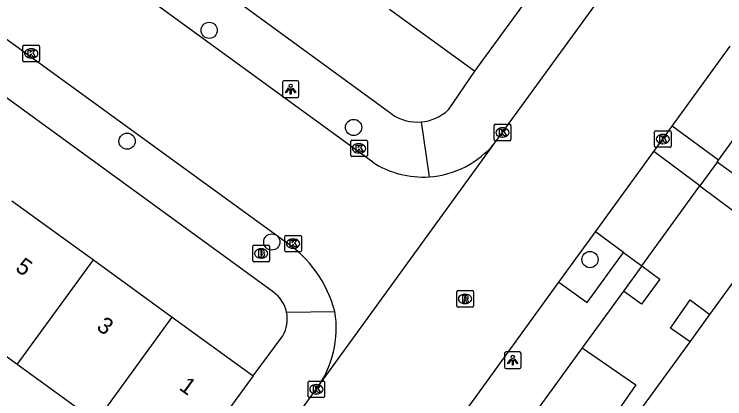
# Model space of a CAD drawing. Extents: x 159675 to 160530, y 382179 to 382901.
# Drawn here: x 160224.11 to 160266.94, y 382538.52 to 382561.72 of the extents above; entities that cross this region are included whole.
import ezdxf

# ---------------------------------------------------------------- set-up
doc = ezdxf.new("R2010")
doc.units = 0
for name, color, linetype in [('IMGEO_Boom', 7, 'Continuous'), ('IMGEO_Brandkraan', 7, 'Continuous'), ('IMGEO_Kolk', 7, 'Continuous'), ('IMGEO_Lichtpunt', 7, 'Continuous'), ('IMGEO_Pand', 7, 'Continuous'), ('IMGEO_Pand_nummerreeks', 7, 'Continuous'), ('IMGEO_Rijbaan_lokaal_gesloten', 7, 'Continuous'), ('IMGEO_Rijbaan_lokaal_open', 7, 'Continuous'), ('IMGEO_Rioolput', 7, 'Continuous'), ('IMGEO_Voetpad_open', 7, 'Continuous')]:
    doc.layers.add(name, color=color, linetype=linetype)

msp = doc.modelspace()

# ---------------------------------------------------------------- linework, layer by layer
at = {"layer": 'IMGEO_Boom'}
for centre in [(160235.859, 382560.746), (160244.564, 382554.886), (160230.912, 382554.058), (160239.635, 382547.977), (160258.813, 382546.917)]:
    msp.add_circle(centre, 0.489, dxfattribs=at)
at = {"layer": 'IMGEO_Brandkraan'}
for p, q in [((160238.567, 382547.789), (160239.419, 382547.789)), ((160238.492, 382546.863), (160238.492, 382547.715)), ((160238.98, 382547.569), (160239.005, 382547.569)), ((160239.493, 382547.715), (160239.493, 382546.863)), ((160239.003, 382547.009), (160238.978, 382547.009)), ((160239.419, 382546.789), (160238.567, 382546.789))]:
    msp.add_line(p, q, dxfattribs=at)
for points in [[(160238.567, 382547.789), (160239.419, 382547.789)], [(160238.492, 382546.863), (160238.492, 382547.715)], [(160238.84, 382547.489), (160238.84, 382547.089), (160239.053, 382547.089)], [(160239.071, 382547.489), (160238.84, 382547.489)], [(160239.019, 382547.408), (160238.965, 382547.408), (160238.965, 382547.332)], [(160238.965, 382547.332), (160239.018, 382547.332)], [(160239.493, 382547.715), (160239.493, 382546.863)], [(160239.027, 382547.256), (160238.965, 382547.256), (160238.965, 382547.175)], [(160238.965, 382547.175), (160239.027, 382547.175)], [(160239.419, 382546.789), (160238.567, 382546.789)]]:
    msp.add_lwpolyline(points, dxfattribs=at)
for centre, radius, start, end in [((160238.569, 382547.713), 0.0765, 91.552, 178.448), ((160238.569, 382547.713), 0.0765, 91.552, 178.448), ((160239.417, 382547.713), 0.0765, 1.552, 88.448), ((160239.417, 382547.713), 0.0765, 1.552, 88.448), ((160239.02, 382547.37), 0.0379, 267.8285, 90.9355), ((160239.075, 382547.344), 0.145, 59.4692, 91.5367), ((160239.1, 382547.391), 0.0922, 285.5137, 58.1501), ((160239.028, 382547.215), 0.0404, 269.8759, 90.5077), ((160239.059, 382547.34), 0.251, 268.6676, 293.5347), ((160239.105, 382547.199), 0.105, 301.3115, 78.989), ((160238.569, 382546.865), 0.0765, 181.552, 268.448), ((160238.569, 382546.865), 0.0765, 181.552, 268.448), ((160239.417, 382546.865), 0.0765, 271.552, 358.448), ((160239.417, 382546.865), 0.0765, 271.552, 358.448)]:
    msp.add_arc(centre, radius, start, end, dxfattribs=at)
for centre, major_axis, ratio, start_param, end_param in [((160238.979, 382547.289), (-0.387, 0.002), 0.722429, 4.712389, 7.853982), ((160239.004, 382547.289), (-0.39, 0.002), 0.717154, 1.570796, 4.712389)]:
    msp.add_ellipse(centre, major_axis=major_axis, ratio=ratio, start_param=start_param, end_param=end_param, dxfattribs=at)
at = {"layer": 'IMGEO_Kolk'}
for p, q in [((160224.634, 382558.926), (160224.634, 382559.778)), ((160224.709, 382559.852), (160225.561, 382559.852)), ((160225.635, 382559.778), (160225.635, 382558.926)), ((160225.122, 382559.632), (160225.147, 382559.632)), ((160225.145, 382559.072), (160225.12, 382559.072)), ((160225.561, 382558.852), (160224.709, 382558.852)), ((160253.113, 382555.086), (160253.965, 382555.086)), ((160253.038, 382554.16), (160253.038, 382555.012)), ((160253.526, 382554.866), (160253.551, 382554.866)), ((160254.039, 382555.012), (160254.039, 382554.16)), ((160262.704, 382553.762), (160262.704, 382554.614)), ((160262.779, 382554.688), (160263.631, 382554.688)), ((160263.705, 382554.614), (160263.705, 382553.762)), ((160253.549, 382554.306), (160253.524, 382554.306)), ((160263.192, 382554.468), (160263.217, 382554.468)), ((160244.394, 382553.201), (160244.394, 382554.053)), ((160244.469, 382554.127), (160245.321, 382554.127)), ((160244.882, 382553.907), (160244.907, 382553.907)), ((160245.395, 382554.053), (160245.395, 382553.201)), ((160253.965, 382554.086), (160253.113, 382554.086)), ((160263.215, 382553.908), (160263.19, 382553.908)), ((160244.905, 382553.347), (160244.88, 382553.347)), ((160263.631, 382553.688), (160262.779, 382553.688)), ((160245.321, 382553.127), (160244.469, 382553.127)), ((160240.418, 382547.453), (160240.418, 382548.305)), ((160240.493, 382548.379), (160241.345, 382548.379)), ((160241.419, 382548.305), (160241.419, 382547.453)), ((160240.906, 382548.159), (160240.931, 382548.159)), ((160241.345, 382547.379), (160240.493, 382547.379)), ((160240.929, 382547.599), (160240.904, 382547.599)), ((160241.82, 382538.669), (160241.82, 382539.521)), ((160241.895, 382539.595), (160242.747, 382539.595)), ((160242.308, 382539.375), (160242.333, 382539.375)), ((160242.821, 382539.521), (160242.821, 382538.669)), ((160242.331, 382538.815), (160242.306, 382538.815)), ((160242.747, 382538.595), (160241.895, 382538.595))]:
    msp.add_line(p, q, dxfattribs=at)
for points in [[(160224.634, 382558.926), (160224.634, 382559.778)], [(160224.709, 382559.852), (160225.561, 382559.852)], [(160225.635, 382559.778), (160225.635, 382558.926)], [(160224.955, 382559.552), (160225.078, 382559.552), (160225.078, 382559.401), (160225.208, 382559.552), (160225.372, 382559.552), (160225.226, 382559.401), (160225.379, 382559.152), (160225.227, 382559.152), (160225.142, 382559.316), (160225.078, 382559.249), (160225.078, 382559.152), (160224.955, 382559.152), (160224.955, 382559.552)], [(160225.561, 382558.852), (160224.709, 382558.852)], [(160253.113, 382555.086), (160253.965, 382555.086)], [(160253.038, 382554.16), (160253.038, 382555.012)], [(160253.359, 382554.786), (160253.482, 382554.786), (160253.482, 382554.635), (160253.612, 382554.786), (160253.776, 382554.786), (160253.63, 382554.635), (160253.783, 382554.386), (160253.631, 382554.386), (160253.546, 382554.55), (160253.482, 382554.483), (160253.482, 382554.386), (160253.359, 382554.386), (160253.359, 382554.786)], [(160254.039, 382555.012), (160254.039, 382554.16)], [(160262.704, 382553.762), (160262.704, 382554.614)], [(160262.779, 382554.688), (160263.631, 382554.688)], [(160263.705, 382554.614), (160263.705, 382553.762)], [(160263.025, 382554.388), (160263.148, 382554.388), (160263.148, 382554.237), (160263.278, 382554.388), (160263.442, 382554.388), (160263.296, 382554.237), (160263.449, 382553.988), (160263.297, 382553.988), (160263.212, 382554.152), (160263.148, 382554.085), (160263.148, 382553.988), (160263.025, 382553.988), (160263.025, 382554.388)], [(160244.394, 382553.201), (160244.394, 382554.053)], [(160244.469, 382554.127), (160245.321, 382554.127)], [(160244.715, 382553.827), (160244.838, 382553.827), (160244.838, 382553.676), (160244.968, 382553.827), (160245.132, 382553.827), (160244.986, 382553.676), (160245.139, 382553.427), (160244.987, 382553.427), (160244.902, 382553.591), (160244.838, 382553.524), (160244.838, 382553.427), (160244.715, 382553.427), (160244.715, 382553.827)], [(160245.395, 382554.053), (160245.395, 382553.201)], [(160253.965, 382554.086), (160253.113, 382554.086)], [(160263.631, 382553.688), (160262.779, 382553.688)], [(160245.321, 382553.127), (160244.469, 382553.127)], [(160240.418, 382547.453), (160240.418, 382548.305)], [(160240.493, 382548.379), (160241.345, 382548.379)], [(160241.419, 382548.305), (160241.419, 382547.453)], [(160240.739, 382548.079), (160240.862, 382548.079), (160240.862, 382547.928), (160240.992, 382548.079), (160241.156, 382548.079), (160241.01, 382547.928), (160241.163, 382547.679), (160241.011, 382547.679), (160240.926, 382547.843), (160240.862, 382547.776), (160240.862, 382547.679), (160240.739, 382547.679), (160240.739, 382548.079)], [(160241.345, 382547.379), (160240.493, 382547.379)], [(160241.82, 382538.669), (160241.82, 382539.521)], [(160241.895, 382539.595), (160242.747, 382539.595)], [(160242.141, 382539.295), (160242.264, 382539.295), (160242.264, 382539.144), (160242.394, 382539.295), (160242.558, 382539.295), (160242.412, 382539.144), (160242.565, 382538.895), (160242.413, 382538.895), (160242.328, 382539.059), (160242.264, 382538.992), (160242.264, 382538.895), (160242.141, 382538.895), (160242.141, 382539.295)], [(160242.821, 382539.521), (160242.821, 382538.669)], [(160242.747, 382538.595), (160241.895, 382538.595)]]:
    msp.add_lwpolyline(points, dxfattribs=at)
for centre, start, end in [((160224.711, 382559.776), 91.552, 178.448), ((160224.711, 382559.776), 91.552, 178.448), ((160225.559, 382559.776), 1.552, 88.448), ((160225.559, 382559.776), 1.552, 88.448), ((160224.711, 382558.928), 181.552, 268.448), ((160224.711, 382558.928), 181.552, 268.448), ((160225.559, 382558.928), 271.552, 358.448), ((160225.559, 382558.928), 271.552, 358.448), ((160253.115, 382555.01), 91.552, 178.448), ((160253.115, 382555.01), 91.552, 178.448), ((160253.963, 382555.01), 1.552, 88.448), ((160253.963, 382555.01), 1.552, 88.448), ((160262.781, 382554.612), 91.552, 178.448), ((160262.781, 382554.612), 91.552, 178.448), ((160263.629, 382554.612), 1.552, 88.448), ((160263.629, 382554.612), 1.552, 88.448), ((160244.471, 382554.051), 91.552, 178.448), ((160244.471, 382554.051), 91.552, 178.448), ((160245.319, 382554.051), 1.552, 88.448), ((160245.319, 382554.051), 1.552, 88.448), ((160253.115, 382554.162), 181.552, 268.448), ((160253.115, 382554.162), 181.552, 268.448), ((160253.963, 382554.162), 271.552, 358.448), ((160253.963, 382554.162), 271.552, 358.448), ((160262.781, 382553.764), 181.552, 268.448), ((160262.781, 382553.764), 181.552, 268.448), ((160263.629, 382553.764), 271.552, 358.448), ((160263.629, 382553.764), 271.552, 358.448), ((160244.471, 382553.203), 181.552, 268.448), ((160244.471, 382553.203), 181.552, 268.448), ((160245.319, 382553.203), 271.552, 358.448), ((160245.319, 382553.203), 271.552, 358.448), ((160240.495, 382548.303), 91.552, 178.448), ((160240.495, 382548.303), 91.552, 178.448), ((160241.343, 382548.303), 1.552, 88.448), ((160241.343, 382548.303), 1.552, 88.448), ((160240.495, 382547.455), 181.552, 268.448), ((160240.495, 382547.455), 181.552, 268.448), ((160241.343, 382547.455), 271.552, 358.448), ((160241.343, 382547.455), 271.552, 358.448), ((160241.897, 382539.519), 91.552, 178.448), ((160241.897, 382539.519), 91.552, 178.448), ((160242.745, 382539.519), 1.552, 88.448), ((160242.745, 382539.519), 1.552, 88.448), ((160241.897, 382538.671), 181.552, 268.448), ((160241.897, 382538.671), 181.552, 268.448), ((160242.745, 382538.671), 271.552, 358.448), ((160242.745, 382538.671), 271.552, 358.448)]:
    msp.add_arc(centre, 0.0765, start, end, dxfattribs=at)
for centre, major_axis, ratio, start_param, end_param in [((160225.121, 382559.352), (-0.387, 0.002), 0.722429, 4.712389, 7.853982), ((160225.146, 382559.352), (-0.39, 0.002), 0.717154, 1.570796, 4.712389), ((160253.525, 382554.586), (-0.387, 0.002), 0.722429, 4.712389, 7.853982), ((160253.55, 382554.586), (-0.39, 0.002), 0.717154, 1.570796, 4.712389), ((160263.191, 382554.188), (-0.387, 0.002), 0.722429, 4.712389, 7.853982), ((160263.216, 382554.188), (-0.39, 0.002), 0.717154, 1.570796, 4.712389), ((160244.881, 382553.627), (-0.387, 0.002), 0.722429, 4.712389, 7.853982), ((160244.906, 382553.627), (-0.39, 0.002), 0.717154, 1.570796, 4.712389), ((160240.905, 382547.879), (-0.387, 0.002), 0.722429, 4.712389, 7.853982), ((160240.93, 382547.879), (-0.39, 0.002), 0.717154, 1.570796, 4.712389), ((160242.307, 382539.095), (-0.387, 0.002), 0.722429, 4.712389, 7.853982), ((160242.332, 382539.095), (-0.39, 0.002), 0.717154, 1.570796, 4.712389)]:
    msp.add_ellipse(centre, major_axis=major_axis, ratio=ratio, start_param=start_param, end_param=end_param, dxfattribs=at)
at = {"layer": 'IMGEO_Lichtpunt'}
for p, q in [((160241.175, 382557.697), (160240.367, 382557.697)), ((160241.175, 382557.697), (160240.367, 382557.697)), ((160240.273, 382557.602), (160240.273, 382556.795)), ((160240.273, 382557.602), (160240.273, 382556.795)), ((160241.269, 382556.795), (160241.269, 382557.602)), ((160241.269, 382556.795), (160241.269, 382557.602)), ((160240.367, 382556.701), (160241.175, 382556.701)), ((160240.367, 382556.701), (160241.175, 382556.701)), ((160254.566, 382541.346), (160253.758, 382541.346)), ((160254.566, 382541.346), (160253.758, 382541.346)), ((160253.664, 382541.251), (160253.664, 382540.444)), ((160253.664, 382541.251), (160253.664, 382540.444)), ((160254.66, 382540.444), (160254.66, 382541.251)), ((160254.66, 382540.444), (160254.66, 382541.251)), ((160253.758, 382540.35), (160254.566, 382540.35)), ((160253.758, 382540.35), (160254.566, 382540.35))]:
    msp.add_line(p, q, dxfattribs=at)
for points in [[(160240.647, 382557.266), (160240.686, 382557.238), (160240.498, 382556.976), (160240.46, 382557.003), (160240.647, 382557.266)], [(160240.749, 382557.218), (160240.796, 382557.218), (160240.796, 382556.896), (160240.749, 382556.896), (160240.749, 382557.218)], [(160240.859, 382557.238), (160240.897, 382557.265), (160241.084, 382557.003), (160241.045, 382556.975), (160240.859, 382557.238)], [(160254.038, 382540.915), (160254.077, 382540.887), (160253.889, 382540.625), (160253.851, 382540.652), (160254.038, 382540.915)], [(160254.25, 382540.887), (160254.288, 382540.914), (160254.475, 382540.652), (160254.436, 382540.624), (160254.25, 382540.887)], [(160254.14, 382540.867), (160254.187, 382540.867), (160254.187, 382540.545), (160254.14, 382540.545), (160254.14, 382540.867)]]:
    msp.add_lwpolyline(points, dxfattribs=at)
for centre in [(160240.772, 382557.4), (160254.163, 382541.049)]:
    msp.add_circle(centre, 0.0994, dxfattribs=at)
for centre, start, end in [((160240.367, 382557.602), 90, 180), ((160240.367, 382557.602), 90, 180), ((160241.175, 382557.602), 0, 90), ((160241.175, 382557.602), 0, 90), ((160240.367, 382556.795), 180, 270), ((160240.367, 382556.795), 180, 270), ((160241.175, 382556.795), 270, 0), ((160241.175, 382556.795), 270, 360), ((160253.758, 382541.251), 90, 180), ((160253.758, 382541.251), 90, 180), ((160254.566, 382541.251), 0, 90), ((160254.566, 382541.251), 0, 90), ((160253.758, 382540.444), 180, 270), ((160253.758, 382540.444), 180, 270), ((160254.566, 382540.444), 270, 0), ((160254.566, 382540.444), 270, 360)]:
    msp.add_arc(centre, 0.0946, start, end, dxfattribs=at)
at = {"layer": 'IMGEO_Pand'}
for points in [[(160256.431, 382564.573), (160251.85, 382558.275)], [(160251.85, 382558.275), (160246.728, 382562)], [(160223.969, 382550.469), (160228.884, 382546.895)], [(160266.042, 382543.613), (160270.111, 382549.224)], [(160224.295, 382540.586), (160228.884, 382546.895)], [(160228.884, 382546.895), (160233.636, 382543.439)], [(160224.295, 382540.586), (160219.38, 382544.16)], [(160264.849, 382541.967), (160266.042, 382543.613)], [(160229.047, 382537.13), (160233.636, 382543.439)], [(160233.636, 382543.439), (160238.502, 382539.899)], [(160259.779, 382534.976), (160264.849, 382541.967)], [(160229.047, 382537.13), (160224.295, 382540.586)], [(160238.502, 382539.899), (160233.913, 382533.59)]]:
    msp.add_lwpolyline(points, dxfattribs=at)
at = {"layer": 'IMGEO_Rijbaan_lokaal_gesloten'}
for points in [[(160253.079, 382553.951), (160253.466, 382554.485), (160263.507, 382568.309)], [(160263.762, 382554.959), (160267.262, 382559.788)], [(160262.654, 382553.43), (160263.762, 382554.959)], [(160242.339, 382539.119), (160253.079, 382553.951)], [(160259.145, 382548.59), (160262.654, 382553.43)], [(160256.944, 382545.554), (160259.145, 382548.59)], [(160249.155, 382534.809), (160256.944, 382545.554)], [(160232.376, 382525.365), (160242.339, 382539.119)]]:
    msp.add_lwpolyline(points, dxfattribs=at)
at = {"layer": 'IMGEO_Rijbaan_lokaal_open'}
for points in [[(160245.716, 382552.786), (160140.763, 382629.192), (160140.555, 382629.351)], [(160136.439, 382623.587), (160136.712, 382623.379), (160240.412, 382548.029)]]:
    msp.add_lwpolyline(points, dxfattribs=at)
for centre, radius, start, end in [((160248.746, 382557.494), 5.597, 273.8234, 320.733), ((160248.746, 382557.503), 5.607, 237.285, 273.8121), ((160236.311, 382541.905), 7.37, 14.8164, 56.1899), ((160237.222, 382542.785), 6.295, 324.3819, 9.1849)]:
    msp.add_arc(centre, radius, start, end, dxfattribs=at)
at = {"layer": 'IMGEO_Rioolput'}
for p, q in [((160250.785, 382544.122), (160250.785, 382544.974)), ((160250.86, 382545.048), (160251.712, 382545.048)), ((160251.273, 382544.828), (160251.298, 382544.828)), ((160251.786, 382544.974), (160251.786, 382544.122)), ((160251.712, 382544.048), (160250.86, 382544.048)), ((160251.296, 382544.268), (160251.271, 382544.268))]:
    msp.add_line(p, q, dxfattribs=at)
for points in [[(160250.785, 382544.122), (160250.785, 382544.974)], [(160250.86, 382545.048), (160251.712, 382545.048)], [(160251.786, 382544.974), (160251.786, 382544.122)], [(160251.374, 382544.746), (160251.122, 382544.748), (160251.122, 382544.348)], [(160251.122, 382544.348), (160251.246, 382544.348), (160251.246, 382544.51), (160251.257, 382544.51)], [(160251.3, 382544.667), (160251.246, 382544.667), (160251.246, 382544.586)], [(160251.246, 382544.586), (160251.298, 382544.586)], [(160251.304, 382544.481), (160251.375, 382544.348), (160251.515, 382544.348), (160251.45, 382544.474)], [(160251.712, 382544.048), (160250.86, 382544.048)]]:
    msp.add_lwpolyline(points, dxfattribs=at)
for centre, radius, start, end in [((160250.862, 382544.972), 0.0765, 91.552, 178.448), ((160250.862, 382544.972), 0.0765, 91.552, 178.448), ((160251.71, 382544.972), 0.0765, 1.552, 88.448), ((160251.71, 382544.972), 0.0765, 1.552, 88.448), ((160251.256, 382544.457), 0.0533, 26.0293, 88.6989), ((160251.282, 382544.775), 0.19, 274.7715, 282.9687), ((160251.306, 382544.571), 0.0964, 77.0061, 93.1865), ((160251.32, 382544.628), 0.0378, 276.6634, 79.6772), ((160251.373, 382544.636), 0.109, 350.3612, 89.416), ((160251.371, 382544.636), 0.112, 277.5842, 350.9817), ((160251.355, 382544.421), 0.108, 29.5134, 73.7905), ((160250.862, 382544.124), 0.0765, 181.552, 268.448), ((160250.862, 382544.124), 0.0765, 181.552, 268.448), ((160251.71, 382544.124), 0.0765, 271.552, 358.448), ((160251.71, 382544.124), 0.0765, 271.552, 358.448)]:
    msp.add_arc(centre, radius, start, end, dxfattribs=at)
for centre, major_axis, ratio, start_param, end_param in [((160251.272, 382544.548), (-0.387, 0.002), 0.722429, 4.712389, 7.853982), ((160251.297, 382544.548), (-0.39, 0.002), 0.717154, 1.570796, 4.712389)]:
    msp.add_ellipse(centre, major_axis=major_axis, ratio=ratio, start_param=start_param, end_param=end_param, dxfattribs=at)
at = {"layer": 'IMGEO_Voetpad_open'}
for points in [[(160246.891, 382555.658), (160224.48, 382572.038)], [(160239.728, 382544.943), (160216.898, 382561.575)], [(160251.85, 382558.275), (160250.273, 382555.941)], [(160266.556, 382552.908), (160269.982, 382557.625)], [(160248.631, 382555.219), (160249.119, 382551.909)], [(160266.556, 382552.908), (160263.762, 382554.959)], [(160265.433, 382551.363), (160262.654, 382553.43)], [(160266.478, 382552.801), (160266.556, 382552.908)], [(160266.478, 382552.801), (160265.433, 382551.363)], [(160265.433, 382551.363), (160268.508, 382549.076), (160269.594, 382550.536), (160266.478, 382552.801)], [(160261.93, 382546.54), (160265.433, 382551.363)], [(160260.836, 382547.345), (160259.145, 382548.59)], [(160256.944, 382545.554), (160258.645, 382544.321), (160260.836, 382547.345)], [(160260.836, 382547.345), (160261.93, 382546.54)], [(160261.93, 382546.54), (160263.031, 382545.73), (160261.924, 382544.225), (160260.827, 382545.022)], [(160261.93, 382546.54), (160260.827, 382545.022)], [(160260.827, 382545.022), (160258.34, 382541.598)], [(160264.849, 382541.967), (160263.67, 382542.781), (160264.845, 382544.481), (160266.042, 382543.613)], [(160240.526, 382543.743), (160243.436, 382543.79)], [(160238.502, 382539.899), (160240.295, 382542.32)], [(160258.34, 382541.598), (160261.573, 382539.364), (160256.263, 382531.683), (160252.908, 382534.119)], [(160258.34, 382541.598), (160252.908, 382534.119)]]:
    msp.add_lwpolyline(points, dxfattribs=at)
for centre, radius, start, end in [((160248.4, 382557.973), 2.764, 274.8002, 312.6707), ((160248.399, 382557.966), 2.756, 236.8423, 274.8374), ((160238.59, 382543.321), 1.982, 12.3047, 54.9431), ((160238.595, 382543.326), 1.975, 329.3782, 12.1807)]:
    msp.add_arc(centre, radius, start, end, dxfattribs=at)

# ---------------------------------------------------------------- texts
at = {"layer": 'IMGEO_Pand_nummerreeks'}
for s, p in [('5', (160224.119, 382546.303)), ('3', (160229.011, 382542.745)), ('1', (160233.996, 382539.12))]:
    msp.add_text(s, height=1, rotation=323.9697, dxfattribs=at).set_placement(p)

doc.saveas('drawing.dxf')
